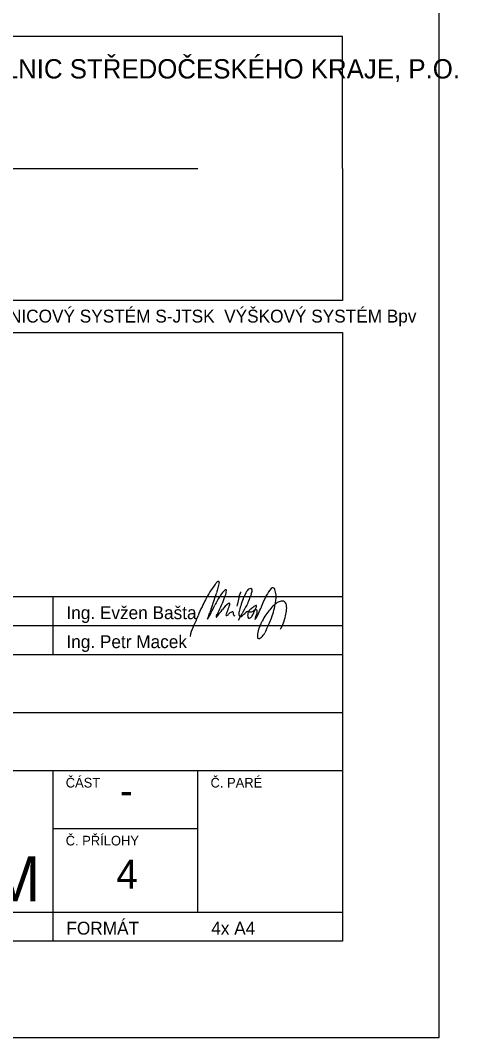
# Model space of a CAD drawing. Extents: x -740053 to -737481, y -1033516 to -1032488.
# Drawn here: x -737514.6 to -737480.7, y -1032955.3 to -1032876.3 of the extents above; entities that cross this region are included whole.
import ezdxf

# ---------------------------------------------------------------- set-up
doc = ezdxf.new("R2010")
doc.units = 0
for name, color, linetype in [('_MIKA', 7, 'Continuous'), ('promika-formát', 7, 'Continuous'), ('promika-rozp', 7, 'Continuous'), ('promika-rozp-text-firmy', 7, 'Continuous')]:
    doc.layers.add(name, color=color, linetype=linetype)

msp = doc.modelspace()

# ---------------------------------------------------------------- linework, layer by layer
at = {"layer": '_MIKA'}
msp.add_lwpolyline([(-737497.689, -1032922.852), (-737497.4, -1032922.326)], dxfattribs=at)
for centre, radius, start, end in [((-737493.807, -1032924.479), 7.198, 142.23523, 153.41785), ((-737481.1, -1032934.323), 23.272, 141.62525, 142.23523), ((-737485.023, -1032923.891), 14.699, 164.31686, 167.58851), ((-737499.251, -1032919.949), 0.119, 77.65258, 141.62525), ((-737499.24, -1032919.899), 0.068, 344.31686, 77.65258), ((-737541.529, -1032906.762), 44.406, 340.28609, 341.66347), ((-737493.392, -1032924.608), 6.785, 146.97351, 154.45028), ((-737508.482, -1032917.542), 10.355, 333.90134, 340.8079), ((-737497.383, -1032922.014), 2.025, 132.28695, 146.97351), ((-737498.666, -1032920.583), 0.104, 95.68301, 139.83775), ((-737500.102, -1032920.455), 1.483, 340.68391, 357.12395), ((-737498.665, -1032920.522), 0.0444, 349.81416, 105.49835), ((-737498.35, -1032920.796), 0.767, 337.07897, 353.18058), ((-737497.124, -1032920.943), 0.468, 139.22083, 173.18058), ((-737501.457, -1032919.018), 4.673, 332.41674, 338.14258), ((-737496.314, -1032921.081), 0.869, 143.70851, 158.14258), ((-737341.363, -1032983.186), 167.377, 158.12382, 158.43787), ((-737496.632, -1032920.847), 0.474, 99.82381, 143.70851), ((-737496.75, -1032920.505), 0.13, 357.13165, 73.63723), ((-737497.578, -1032920.463), 0.96, 338.12382, 357.13165), ((-737489.658, -1032924.011), 6.616, 152.29875, 159.50378), ((-737492.973, -1032922.271), 2.872, 139.05622, 152.29875), ((-737495.012, -1032920.502), 0.173, 15.21404, 139.05622), ((-737496.658, -1032921.032), 1.902, 351.39073, 17.62988), ((-737493.455, -1032925.272), 7.866, 153.77616, 159.46538), ((-737414.267, -1032964.278), 96.139, 153.41785, 153.77616), ((-737516.15, -1032913.729), 18.439, 330.61841, 334.45028), ((-737478.729, -1032929.265), 22.304, 160.28609, 161.69166), ((-737497.374, -1032923.084), 1.885, 124.89597, 145.05699), ((-737493.071, -1032923.854), 5.731, 157.76834, 162.23546), ((-737498.408, -1032921.601), 0.0779, 55.10403, 124.89597), ((-737498.608, -1032921.591), 0.25, 337.76834, 12.42518), ((-737494.715, -1032922.328), 3.146, 165.90811, 169.54357), ((-737478.313, -1032926.445), 20.058, 164.53011, 165.90811), ((-737483.316, -1032926.163), 14.867, 162.64406, 164.43328), ((-737489.12, -1032924.349), 8.786, 158.86527, 162.64406), ((-737478.612, -1032932.638), 21.433, 149.22929, 151.24035), ((-737494.95, -1032924), 2.686, 125.81479, 133.21132), ((-737495.268, -1032923.56), 2.144, 119.74147, 125.81479), ((-737496.31, -1032921.735), 0.0415, 339.1031, 119.74147), ((-737501.996, -1032919.564), 6.128, 338.12374, 339.1031), ((-737502.288, -1032919.29), 6.867, 335.01458, 339.50378), ((-737490.368, -1032926.136), 6.376, 135.47239, 144.29948), ((-737502.392, -1032920.164), 7.701, 342.2433, 351.39073), ((-737494.11, -1032922.456), 1.128, 115.27288, 135.47239), ((-737494.245, -1032922.169), 0.811, 93.24087, 115.27288), ((-737494.273, -1032921.668), 0.309, 16.61177, 93.24087), ((-737494.96, -1032921.873), 1.026, 352.45357, 16.61177), ((-737510.197, -1032919.001), 10.012, 334.10342, 339.46538), ((-737521.079, -1032915.252), 22.304, 340.28609, 341.69166), ((-737499.399, -1032922.599), 0.0218, 175.43081, 341.96748), ((-737499.156, -1032922.619), 0.266, 150.33743, 175.43081), ((-737504.628, -1032919.502), 6.032, 330.33743, 334.51836), ((-737506.532, -1032916.685), 9.287, 320.38725, 325.05699), ((-737498.516, -1032922.407), 0.143, 157.34282, 210.29061), ((-737496.34, -1032923.315), 2.501, 151.08165, 157.34281), ((-737498.658, -1032922.213), 0.266, 274.06523, 322.04071), ((-737498.037, -1032922.698), 0.522, 109.96924, 142.04071), ((-737498.166, -1032922.291), 0.0966, 16.46783, 120.57707), ((-737499.54, -1032922.532), 1.491, 4.64701, 10.37671), ((-737497.962, -1032922.413), 0.0917, 178.87234, 265.72159), ((-737497.153, -1032922.309), 0.503, 164.43328, 200.27708), ((-737497.518, -1032922.443), 0.115, 200.27708, 295.62005), ((-737498.96, -1032920.437), 2.584, 305.25171, 313.28111), ((-737496.383, -1032923.173), 1.174, 123.9927, 133.28111), ((-737496.982, -1032922.247), 0.0751, 330.79764, 140.06184), ((-737496.78, -1032922.548), 0.174, 168.44211, 226.63633), ((-737499.031, -1032922.087), 2.124, 348.4421, 354.69045), ((-737496.857, -1032922.468), 0.211, 258.27689, 327.55364), ((-737496.841, -1032922.163), 0.0443, 160.07678, 271.04324), ((-737496.762, -1032922.192), 0.128, 132.49991, 160.07678), ((-737501.259, -1032917.285), 6.527, 312.49991, 313.21132), ((-737496.861, -1032921.084), 1.123, 271.04324, 277.1213), ((-737496.771, -1032921.802), 0.4, 277.1213, 296.25137), ((-737322.282, -1033033.454), 206.658, 147.46165, 147.55364), ((-737496.811, -1032921.722), 0.489, 296.25137, 309.92826), ((-737510.08, -1032916.318), 14.839, 336.22301, 338.12374), ((-737496.267, -1032922.371), 0.357, 114.58049, 129.92826), ((-737496.338, -1032922.218), 0.188, 88.02122, 114.58049), ((-737497.414, -1032921.938), 1.33, 321.43729, 335.0016), ((-737497.507, -1032922.255), 1.216, 341.13101, 346.95348), ((-737496.338, -1032922.24), 0.211, 61.49258, 88.02122), ((-737495.647, -1032922.686), 0.693, 155.07666, 166.95348), ((-737496.84, -1032922.132), 0.622, 335.07666, 354.59191), ((-737496.534, -1032922.161), 0.315, 354.59191, 19.66909), ((-738862.563, -1032285.405), 1507.586, 335.001598, 335.014577), ((-737493.264, -1032924.055), 2.811, 144.29948, 156.17031), ((-737499.954, -1032920.945), 5.141, 333.88055, 342.2433), ((-737497.444, -1032921.815), 3.487, 330.20089, 348.45026), ((-737501.204, -1032921.046), 7.325, 348.45026, 352.45357), ((-737499.52, -1032924.334), 1.927, 150.11086, 172.99111), ((-737496.382, -1032922.769), 0.00871, 166.95348, 13.04652), ((-737495.206, -1032923.042), 1.216, 161.13101, 166.95348), ((-737494.008, -1032924.287), 2.232, 154.16547, 167.44743), ((-737507.194, -1032917.903), 12.418, 334.16547, 336.17031), ((-734241.505, -1034518.614), 3623.913, 153.880552, 153.891528), ((-737495.323, -1032924.025), 0.892, 165.54134, 191.72704), ((-737496.093, -1032924.158), 0.114, 204.62312, 301.34548), ((-737496.307, -1032923.695), 0.623, 296.02507, 312.0858), ((-737496.614, -1032923.356), 1.081, 312.0858, 333.89153)]:
    msp.add_arc(centre, radius, start, end, dxfattribs=at)
at = {"layer": 'promika-formát'}
msp.add_lwpolyline([(-737587.097, -1032955.262), (-737482.097, -1032955.262), (-737482.097, -1032806.762), (-737587.097, -1032806.762)], close=True, dxfattribs=at)
at = {"layer": 'promika-rozp'}
for p, q in [((-737579.597, -1032921.012), (-737489.597, -1032921.012)), ((-737512.097, -1032921.012), (-737512.097, -1032925.512)), ((-737579.597, -1032923.262), (-737489.597, -1032923.262)), ((-737579.597, -1032925.512), (-737489.597, -1032925.512)), ((-737579.597, -1032930.012), (-737489.597, -1032930.012)), ((-737579.597, -1032934.512), (-737489.597, -1032934.512)), ((-737512.097, -1032934.512), (-737512.097, -1032947.762)), ((-737500.847, -1032945.512), (-737500.847, -1032934.512)), ((-737512.097, -1032939.012), (-737500.847, -1032939.012)), ((-737579.597, -1032945.512), (-737489.597, -1032945.512))]:
    msp.add_line(p, q, dxfattribs=at)
for points in [[(-737489.597, -1032887.762), (-737489.597, -1032877.512), (-737579.597, -1032877.512), (-737579.597, -1032887.762)], [(-737489.597, -1032887.762), (-737489.597, -1032898.012), (-737579.597, -1032898.012), (-737579.597, -1032887.762)], [(-737547.421, -1032887.762), (-737500.847, -1032887.762)], [(-737579.597, -1032921.012), (-737579.597, -1032900.512), (-737489.597, -1032900.512), (-737489.597, -1032921.012)], [(-737489.597, -1032921.012), (-737489.597, -1032947.762), (-737579.597, -1032947.762), (-737579.597, -1032921.012)], [(-737579.597, -1032925.512), (-737489.597, -1032925.512)]]:
    msp.add_lwpolyline(points, dxfattribs=at)

# ---------------------------------------------------------------- texts
for s, height, p in [('SOUŘADNICOVÝ SYSTÉM S-JTSK  VÝŠKOVÝ SYSTÉM Bpv', 1, (-737521.229, -1032899.73)), ('Ing. Evžen Bašta', 1, (-737511.046, -1032922.762)), ('Ing. Petr Macek', 1, (-737511.046, -1032925.012)), ('ČÁST', 0.75, (-737511.099, -1032935.837)), ('Č. PARÉ', 0.75, (-737499.849, -1032935.837)), ('-', 2.25, (-737506.891, -1032937.19)), ('Č. PŘÍLOHY', 0.75, (-737511.099, -1032940.337)), ('4', 2.25, (-737507.172, -1032943.69)), ('FORMÁT', 1, (-737511.046, -1032947.262)), ('4x A4', 1, (-737499.796, -1032947.262))]:
    msp.add_text(s, height=height, dxfattribs=at).set_placement(p)
at = {"layer": 'promika-rozp-text-firmy'}
for s, height, p in [('KRAJSKÁ SPRÁVA A ÚDRŽBA SILNIC STŘEDOČESKÉHO KRAJE, P.O.', 1.5, (-737546.901, -1032880.777)), ('DENDROLOGICKÝ PRŮZKUM', 3.5, (-737578.599, -1032944.68))]:
    msp.add_text(s, height=height, dxfattribs=at).set_placement(p)

doc.saveas('drawing.dxf')
